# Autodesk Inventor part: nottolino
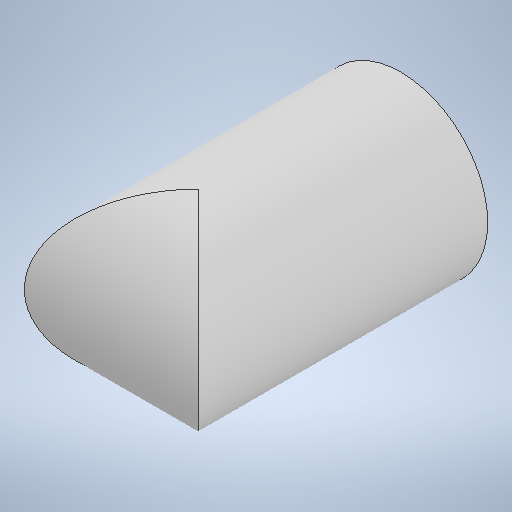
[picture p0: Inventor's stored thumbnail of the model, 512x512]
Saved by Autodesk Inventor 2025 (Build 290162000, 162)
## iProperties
Created: 2025-10
Part Number: nottolino
Material: Generico
Document SubType Name: Modeling
Designer: 18619647
Density: 1 g/cm^3
Appearance: Default
Author: 18619647
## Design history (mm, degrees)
sketch "Schizzo1"
  geometry: C1 r 1.5 at (0, 0); 1 further point
  constraints: 1 centre point, 1 coincident
  dimensions: "d0" = 3 diameter of C1
extrude "Estrusione1" new body sketch "Schizzo1" distance "d1" = 5; taper "d2" = 0 deg
node "Piano di lavoro1"
sketch "Schizzo2"
  geometry: L1 (0, 0)-(0, 5) reference; L2 (1.5, 0)-(1.5, 5) reference; L3 (1.5, 3.5)-(1.5, 6.373); L4 (1.5, 6.373)-(-1.5, 6.373); L5 (-1.5, 6.373)-(-1.5, 3.5); L6 (-1.5, 0)-(-1.5, 5) reference; A1 r 1.5 centre (0, 3.5) between (1.5, 3.5) and (-1.5, 3.5); 1 further point
  constraints: 6 end point, 2 point on circle, 2 point on line, 1 centre point, 1 perpendicular, 1 tangent
  dimensions: "d5" = 3 diameter of A1; "d6" = 3 distance of L3.end L4.end
extrude "Estrusione2" cut sketch "Schizzo2" extent not by distance; stored distance "d7" = 0; taper "d8" = 0 deg
node "Solido1"
node "Proietta spigoli di taglio1"
other parameters: "d3" = 1.5
